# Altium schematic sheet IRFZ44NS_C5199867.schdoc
size 127 x 101 mm
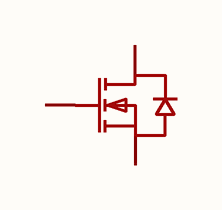
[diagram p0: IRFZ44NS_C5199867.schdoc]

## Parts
Q?  irfz44ns(umw)  [TO-263-2_L10.2-W8.7-P5.08-LS15.1-BL]  (value not drawn)

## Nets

Not connected (* = marked no-connect by the designer): Q? 1(G) 2(D) 3(S)

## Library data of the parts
Q? = irfz44ns(umw): 数量:1个N沟道;漏源电压(Vdss):60V;连续漏极电流(Id):50A;导通电阻(RDS(on)):12mΩ@10V；16mΩ@4.5V;耗散功率(Pd):105W;阈值电压(Vgs(th)):1.6V@250uA;; Manufacturer: UMW(友台半导体); Symbol: IRFZ44NS_C5199867; AddInBom: yes; ModelId: cad6ef07ed97400bb297d975e2ba0c16; ModelTransform: 398.8181,594.487,0,0,0,0,0,44.331,0; Number: 1个N沟道; Drain to Source Voltage: 60V; Current - Continuous Drain(Id): 50A; Pd - Power Dissipation: 105W; Gate Charge(Qg): 50nC@10V; Input Capacitance(Ciss): 2.928nF; Reverse Transfer Capacitance (Crss@Vds): 120pF; Output Capacitance(Coss): 141pF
